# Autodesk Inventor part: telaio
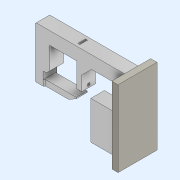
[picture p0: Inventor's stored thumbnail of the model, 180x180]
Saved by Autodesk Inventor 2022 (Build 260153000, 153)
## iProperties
Created: 2022-01
Part Number: telaio
Material: Generico
Document SubType Name: Modeling
Designer: admin
Density: 1 g/cm^3
Appearance: Lavorato - Alluminio
Author: admin
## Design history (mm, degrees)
sketch "Schizzo1"
  geometry: L1 (-129.75, 12.9)-(-129.75, 0) reference; L2 (-149.75, 12.9)-(-149.75, 0); L3 (-255.346, 91.815)-(-255.346, -109.293); L4 (-255.346, -109.293)-(-306.846, -109.293); L5 (-153.75, -164.4)-(-129.75, -164.4) reference; L6 (-306.846, -109.293)-(-306.846, -168.185); L7 (-306.846, -168.185)-(-56.846, -168.185); L8 (-1.846, -174.4)-(48.154, -174.4); L9 (-56.846, -213.185)-(-366.846, -213.185); L10 (-366.846, -213.185)-(-366.846, 91.815); L11 (-366.846, 91.815)-(-255.346, 91.815); L12 (-366.846, 91.815)-(333.154, 91.815); L13 (333.154, 91.815)-(333.154, 191.815); L14 (333.154, 191.815)-(-366.846, 191.815); L15 (-366.846, 191.815)-(-366.846, 91.815); L16 (63.75, -7.086)-(63.75, 39.086) reference; L17 (-41.846, 91.815)-(-1.846, 91.815); L18 (-1.846, 91.815)-(-1.846, -98.185); L19 (-1.846, -98.185)-(-41.846, -98.185); L20 (-41.846, -98.185)-(-41.846, 91.815); L21 (-1.846, 16.815)-(73.154, 91.815); L22 (333.154, 91.815)-(313.154, 91.815); L23 (313.154, 91.815)-(313.154, -408.185); L24 (313.154, -408.185)-(333.154, -408.185); L25 (333.154, -408.185)-(333.154, 91.815); L26 (313.154, -408.185)-(68.154, -408.185); L27 (68.154, -408.185)-(68.154, -108.185); L28 (68.154, -108.185)-(313.154, -108.185); L29 (313.154, -108.185)-(313.154, -408.185); L30 (-56.846, -213.185)-(-56.846, -168.185); 7 further points
  constraints: 54 end point, 9 parallel, 9 perpendicular, 6 horizontal, 3 point on line, 2 vertical
  dimensions: "d0" = 20 distance between parallel lines of L1 L2; "d6" = 700 distance of L14.end L13.end; "d7" = 100 distance of L13.end L12.end; "d8" = 190 distance of L19.end L17.start; "d9" = 75 distance of L17.end L21.start; "d10" = 75 distance of L21.end L17.end; "d20" = 213.5 distance between parallel lines of L20 L3; "d21" = 40 distance of L18.end L19.end; "d24" = 325 distance between parallel lines of L20 L10; "d26" = 60 distance between parallel lines of L10 L6; "d27" = 20 distance of L24.end L23.end; "d28" = 500 distance of L23.end L22.end; "d29" = 300 distance of L26.end L27.end; "d30" = 245 distance of L23.end L26.end; "d44" = 310 distance of L9.start L9.end; "d51" = 305 distance of L9.end L10.end; "d52" = 45 distance between parallel lines of L9 L7
extrude "Estrusione1" new body sketch "Schizzo1" distance "d11" = 107; taper "d12" = 0 deg
sketch "Schizzo2"
  geometry: L1 (325, 0)-(325, 107) reference; L2 (325, 53.5)-(238.532, 53.5); L3 (309.809, 23.5)-(324.809, 23.5); L4 (324.809, 23.5)-(324.809, 83.5); L5 (324.809, 83.5)-(309.809, 83.5); L6 (309.809, 83.5)-(309.809, 23.5); 1 further point
  constraints: 10 end point, 2 horizontal, 2 parallel, 1 midpoint, 1 perpendicular, 1 other
  dimensions: "d13" = 15 distance of L5.end L4.end; "d14" = 60 distance of L4.end L3.end
extrude "Estrusione2" cut sketch "Schizzo2" stored distance "d15" = 0; taper "d16" = 0 deg
chamfer "Smusso1" distance "d17" = 27; stored, may be unused: second distance "d18" = 2, angle "d19" = 45 deg
sketch "Schizzo3"
  geometry: L1 (-255.346, -82.293)-(-282.346, -109.293) reference; L2 (-255.346, -82.293)-(-255.346, 91.815) reference; L3 (-255.346, 91.815)-(-41.846, 91.815) reference; L4 (-41.846, 91.815)-(-41.846, -98.185) reference; L5 (-41.846, -98.185)-(-1.846, -98.185) reference; L6 (-1.846, -98.185)-(-1.846, 16.815) reference; L7 (-1.846, 16.815)-(73.154, 91.815) reference; L8 (73.154, 91.815)-(313.154, 91.815) reference; L9 (333.154, 191.815)-(-366.846, 191.815) reference; L10 (-366.846, 191.815)-(-366.846, -213.185) reference; L11 (-366.846, -213.185)-(-56.846, -213.185) reference; L12 (-56.846, -168.185)-(-306.846, -168.185) reference; L13 (-306.846, -168.185)-(-306.846, -109.293) reference; L14 (-306.846, -109.293)-(-282.346, -109.293) reference; L15 (-306.846, -168.185)-(-306.846, -213.185); L16 (-56.846, -213.185)-(-366.846, -213.185) reference; L17 (313.154, 91.815)-(313.154, -108.185) reference; L18 (333.154, -408.185)-(333.154, 191.815) reference; L19 (313.154, -108.185)-(68.154, -108.185) reference; L20 (68.154, -108.185)-(68.154, -408.185) reference; L21 (68.154, -408.185)-(333.154, -408.185) reference; L22 (-56.846, -213.185)-(-56.846, -168.185) reference; 2 further points
  constraints: 2 end point, 1 perpendicular, 1 point on line
extrude "Estrusione3" cut sketch "Schizzo3" distance "d22" = 10; taper "d23" = 0 deg
node "Piano di lavoro1"
mirror "Specchio1"
sketch "Schizzo4"
  geometry: L1 (0, 0)-(0, 600) reference; L2 (0, 0)-(107, 0) reference; L3 (107, 600)-(107, 0) reference; L4 (0, 600)-(107, 600) reference; L5 (0, 0)-(0, 600) reference; L6 (0, 0)-(-100, 0); L7 (-100, 0)-(-100, 600); L8 (-100, 600)-(0, 600); L9 (0, 600)-(0, 0); L10 (107, 600)-(107, 0) reference; L11 (107, 0)-(207, 0); L12 (207, 0)-(207, 600); L13 (207, 600)-(107, 600); L14 (107, 600)-(107, 0); 3 further points
  constraints: 16 end point, 4 parallel, 2 horizontal, 2 perpendicular, 1 point on line
  dimensions: "d31" = 100 distance of L7.end L8.end; "d32" = 100 distance of L13.end L12.end
extrude "Estrusione4" new body sketch "Schizzo4" distance "d33" = 50; taper "d34" = 0 deg
fillet "Raccordo1" dims "d35" = 1
sketch "Schizzo5"
  geometry: L1 (52.5, -93.1)-(52.5, -42.753); L2 (42.5, -81.831)-(62.5, -81.831); L3 (62.5, -81.831)-(62.5, -101.831); L4 (62.5, -101.831)-(42.5, -101.831); L5 (42.5, -101.831)-(42.5, -81.831); C1 r 3.845 at (52.5, -93.1) reference; 1 further point
  constraints: 10 end point, 2 parallel, 1 horizontal, 1 perpendicular, 1 vertical, 1 other
  dimensions: "d36" = 20 distance of L3.end L4.end; "d37" = 20 distance of L2.end L3.end
extrude "Estrusione5" cut sketch "Schizzo5" distance "d38" = 10; taper "d39" = 0 deg
fillet "Raccordo2" dims "d40" = 4
chamfer "Smusso2" distance "d41" = 4; stored, may be unused: second distance "d42" = 2, angle "d43" = 45 deg
chamfer "Smusso3" distance "d45" = 10; stored, may be unused: second distance "d46" = 2, angle "d47" = 45 deg
chamfer "Smusso4" distance "d48" = 60; stored, may be unused: second distance "d49" = 2, angle "d50" = 30 deg
node "Solido1"
node "Riferimento1"
node "Riferimento2"
node "Riferimento3"
node "Linea chiusa proiettata1"
node "Linea chiusa proiettata2"
node "Solido2"
node "Riferimento4"
